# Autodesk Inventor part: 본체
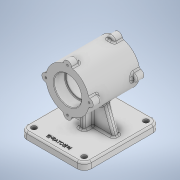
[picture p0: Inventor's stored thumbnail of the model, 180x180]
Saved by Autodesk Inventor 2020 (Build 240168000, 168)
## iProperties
Created: 2022-11
Part Number: 본체
Material: 일반
Document SubType Name: Modeling
Designer: owner
Density: 1 g/cm^3
Appearance: 기본값
Author: owner
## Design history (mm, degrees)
sketch "스케치1"
  geometry: L1 (-55, 65)-(55, 65); L2 (55, 65)-(55, -65); L3 (55, -65)-(-55, -65); L4 (-55, -65)-(-55, 65); L5 (-55, 65)-(55, -65); L6 (55, 65)-(-55, -65); 1 further point
  constraints: 12 end point, 2 midpoint, 2 parallel, 1 horizontal, 1 perpendicular
  dimensions: "d0" = 110 distance of L2.end L3.end; "d1" = 130 distance of L1.end L2.end
extrude "돌출1" new body sketch "스케치1" distance "d2" = 12; taper "d3" = 0 deg
node "작업 평면1"
sketch "스케치2"
  geometry: L1 (0, 0)-(110, 0) reference; C1 r 37 at (55, 82); 2 further points
  constraints: 1 centre point, 1 midpoint, 1 vertical alignment
  dimensions: "d5" = 74 diameter of C1; "d6" = 82 distance from line of L1 C1.centre
extrude "돌출2" join sketch "스케치2" stored distance "d7" = 87; taper "d8" = 0 deg
sketch "스케치3"
  geometry: L1 (37, 0)-(-37, 0); L2 (0, 37)-(0, -37); C1 r 7 at (0, 37); C2 r 7 at (37, 0); C3 r 7 at (0, -37); C4 r 7 at (-37, 0); A1 r 37 centre (0, 0) between (0, 37) and (37, 0) reference; 9 further points
  constraints: 4 centre point, 4 end point, 4 point on circle, 1 horizontal, 1 horizontal alignment, 1 perpendicular, 1 vertical alignment, 2 other
  dimensions: "d9" = 14 diameter of C1; "d10" = 14 diameter of C2
extrude "돌출3" join sketch "스케치3" distance "d11" = 14; taper "d12" = 0 deg
sketch "스케치4"
  geometry: A1 r 37 centre (55, 82) between (91.338, 88.969) and (61.969, 118.338) reference; 2 further points
  constraints: 1 coincident
hole "구멍1" sketch "스케치4" at (55, 82) diameter "d13" = 42; stored, may be unused: countersink angle "d17" = 90 deg, drill point angle "d19" = 0 deg; dims "d14" = 12, "d15" = 47, "d16" = 19, "d18" = 8
sketch "스케치5"
  geometry: A1 r 37 centre (-55, 82) between (-48.031, 45.662) and (-18.662, 75.031) reference; 2 further points
  constraints: 1 coincident
hole "구멍2" sketch "스케치5" at (-55, 82) diameter "d20" = 42; stored, may be unused: countersink angle "d24" = 90 deg, drill point angle "d26" = 0 deg; dims "d21" = 12, "d22" = 47, "d23" = 19, "d25" = 8
sketch "스케치7"
  geometry: A1 r 7 centre (55, 119) between (61.969, 118.338) and (48.031, 118.338) reference; A2 r 7 centre (92, 82) between (91.338, 75.031) and (91.338, 88.969) reference; A3 r 7 centre (55, 45) between (48.031, 45.662) and (61.969, 45.662) reference; A4 r 7 centre (18, 82) between (18.662, 88.969) and (18.662, 75.031) reference; 5 further points
  constraints: 4 coincident
hole "구멍3" sketch "스케치7" at (55, 119), (92, 82), (55, 45), (18, 82) diameter "d28" = 3.242; stored, may be unused: countersink angle "d32" = 90 deg, drill point angle "d34" = 118 deg; dims "d29" = 8, "d30" = 47, "d31" = 19, "d33" = 10
sketch "스케치8"
  geometry: L1 (110, 0)-(0, 0) reference; L2 (0, 0)-(0, 12) reference; L3 (110, 12)-(0, 12) reference; L4 (110, 0)-(110, 12) reference; L5 (110, 12)-(0, 12) reference; L6 (14, 12)-(29.664, 55.036); L7 (96, 12)-(80.336, 55.036); A1 r 37 centre (55, 82) between (18.662, 75.031) and (48.031, 45.662) reference; A2 r 37 centre (55, 82) between (61.969, 45.662) and (91.338, 75.031) reference; A3 r 37 centre (55, 82) between (48.031, 45.662) and (61.969, 45.662) reference; 3 further points
  constraints: 4 end point, 2 point on circle, 2 point on line
  dimensions: "d35" = 110 deg angle of L3 L6; "d36" = 110 deg angle of L3 L7; "d37" = 14 distance of L2.end L6.start; "d38" = 14 distance of L7.start L3.start
extrude "돌출4" join sketch "스케치8" stored distance "d39" = 10; taper "d40" = 0 deg
sketch "스케치9"
  geometry: L1 (12, -65)-(12, 65) reference; L2 (12, 15)-(27.559, 15); L3 (12, 0)-(12, -10) reference; L4 (55.036, 0)-(12, 0) reference; L5 (55.036, -10)-(55.036, 0) reference; L6 (12, -10)-(55.036, -10) reference; 2 further points
  constraints: 2 end point, 1 horizontal, 1 midpoint, 1 point on line
  dimensions: "d41" = 20 distance of L2.start point (12, -5)
feature "리브1" sketch "스케치9" dims "d42" = 1, "d43" = 10, "d44" = 0, "d45" = 0, "d46" = 1, "d47" = 1
fillet "모깎기1" dims "d48" = 12
fillet "모깎기2" dims "d49" = 3
fillet "모깎기3" dims "d50" = 3
fillet "모깎기4" dims "d51" = 3
fillet "모깎기5" dims "d52" = 3
fillet "모깎기6" dims "d53" = 3
fillet "모깎기7" dims "d54" = 3
fillet "모깎기8" dims "d55" = 3
fillet "모깎기9" dims "d56" = 3
fillet "모깎기10" dims "d57" = 1
chamfer "모따기1" distance "d58" = 1; stored, may be unused: second distance "d59" = 2, angle "d60" = 45 deg
sketch "스케치10"
  geometry: A1 r 12 centre (-43, 53) between (-43, 65) and (-55, 53) reference; A2 r 12 centre (43, 53) between (55, 53) and (43, 65) reference; A3 r 12 centre (-43, -53) between (-55, -53) and (-43, -65) reference; A4 r 12 centre (43, -53) between (43, -65) and (55, -53) reference; 5 further points
  constraints: 4 coincident
hole "구멍4" sketch "스케치10" at (-43, 53), (43, 53), (-43, -53), (43, -53) diameter "d61" = 9; stored, may be unused: countersink angle "d65" = 90 deg, drill point angle "d67" = 0 deg; dims "d62" = 8, "d63" = 47, "d64" = 19, "d66" = 10
sketch "스케치11"
  geometry: L1 (77, 5)-(-77, 5) reference; L2 (43, -62)-(-43, -62) reference; 3 further points
  constraints: 1 midpoint, 1 vertical alignment, 1 other
  dimensions: "d68" = 58 distance from line of L1 point (0, -53)
feature "엠보싱1" sketch "스케치11" dims "d0" = 110, "d1" = 130, "d9" = 14, "d10" = 14, "d69" = 0.5, "d70" = 0
node "솔리드1"
mirror "미러1"
mirror "미러2"
mirror "미러3"
node "투영된 루프1"
node "투영된 루프2"
feature "A9D066F2-1C7D-4E18-AEED-F7BC21143FA4" dims "d13" = 42, "d14" = 12, "d15" = 47, "d16" = 19, "d17" = 90 deg, "d18" = 8, "d19" = 0
